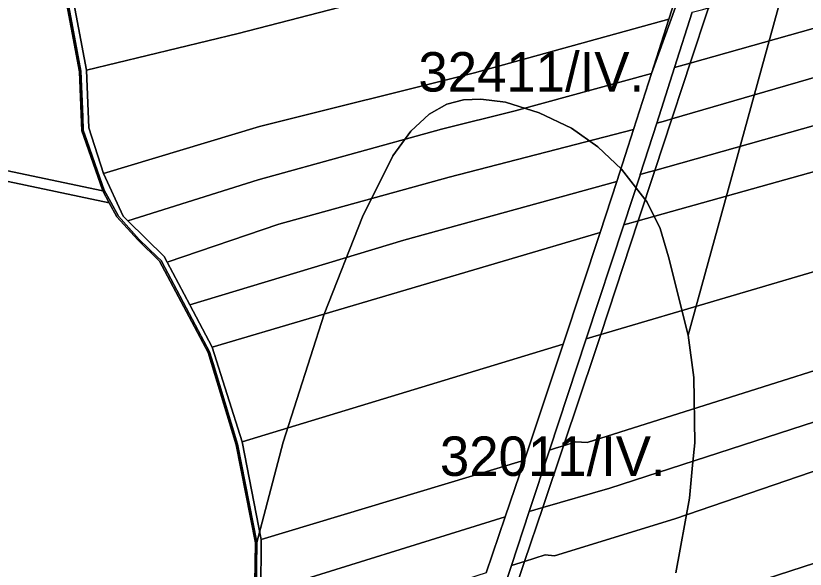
# Model space of a CAD drawing. Extents: x -535894 to -532827, y -1165802 to -1163635.
# Drawn here: x -534170.3 to -533869.9, y -1164231.2 to -1164020.6 of the extents above; entities that cross this region are included whole.
import ezdxf

# ---------------------------------------------------------------- set-up
doc = ezdxf.new("R2010")
doc.units = 0
for name, color, linetype in [('BPEJ_s', 7, 'Continuous'), ('orna_s', 7, 'Continuous'), ('ostatni_s', 7, 'Continuous'), ('PUPFL_s', 7, 'Continuous')]:
    doc.layers.add(name, color=color, linetype=linetype)

msp = doc.modelspace()

# ---------------------------------------------------------------- linework, layer by layer
at = {"layer": 'BPEJ_s'}
for points in [[(-533875.366, -1164000), (-533914.47, -1164142.17), (-533921.943, -1164112.324), (-533924.425, -1164103.745), (-533925.06, -1164101.55), (-533930.08, -1164091.52), (-533939.763, -1164078.96), (-533948.79, -1164070.49), (-533958.872, -1164063.308), (-533971.09, -1164057.51), (-533983.99, -1164053.45), (-533993.341, -1164052.28), (-533999.92, -1164052.57), (-534006.29, -1164054.239), (-534012.98, -1164057.99), (-534019.91, -1164064.519), (-534026.76, -1164073.91), (-534038.39, -1164097.17), (-534052.88, -1164134.121), (-534068.49, -1164182.86), (-534078.523, -1164221.003), (-534085.899, -1164183.652), (-534088.342, -1164175.577), (-534095.182, -1164152.964), (-534096.544, -1164148.462), (-534100.815, -1164140.418), (-534113.603, -1164116.335), (-534114.995, -1164113.714), (-534116.451, -1164112.304), (-534123.297, -1164105.677), (-534131.206, -1164096.91), (-534134.129, -1164091.534), (-534136.591, -1164086.985), (-534140.179, -1164076.764), (-534143.251, -1164068.015), (-534144.622, -1164064.109), (-534144.816, -1164059.106), (-534145.49, -1164041.708), (-534153.303, -1164000)], [(-534153.303, -1164000), (-534145.49, -1164041.708), (-534144.816, -1164059.106), (-534144.622, -1164064.109), (-534143.251, -1164068.015), (-534140.179, -1164076.764), (-534136.591, -1164086.985), (-534134.129, -1164091.534), (-534131.206, -1164096.91), (-534123.297, -1164105.677), (-534116.451, -1164112.304), (-534114.995, -1164113.714), (-534113.603, -1164116.335), (-534100.815, -1164140.418), (-534096.544, -1164148.462), (-534095.182, -1164152.964), (-534088.342, -1164175.577), (-534085.899, -1164183.652), (-534078.523, -1164221.003), (-534078.967, -1164248.905)], [(-533919.09, -1164232.56), (-533913.99, -1164204.13), (-533912.751, -1164191.59), (-533911.92, -1164183.18), (-533912.32, -1164158.25), (-533914.47, -1164142.17), (-533875.366, -1164000)], [(-534078.967, -1164248.905), (-534078.523, -1164221.003), (-534068.49, -1164182.86), (-534052.88, -1164134.121), (-534038.39, -1164097.17), (-534026.76, -1164073.91), (-534019.91, -1164064.519), (-534012.98, -1164057.99), (-534006.29, -1164054.239), (-533999.92, -1164052.57), (-533993.341, -1164052.28), (-533983.99, -1164053.45), (-533971.09, -1164057.51), (-533958.872, -1164063.308), (-533948.79, -1164070.49), (-533939.763, -1164078.96), (-533930.08, -1164091.52), (-533925.06, -1164101.55), (-533924.425, -1164103.745), (-533921.943, -1164112.324), (-533914.47, -1164142.17), (-533912.32, -1164158.25), (-533911.92, -1164183.18), (-533912.751, -1164191.59), (-533913.99, -1164204.13), (-533919.09, -1164232.56)]]:
    msp.add_lwpolyline(points, dxfattribs=at)
at = {"layer": 'orna_s'}
for points in [[(-533895.7, -1163940.37), (-533908.87, -1163981.51), (-534085.67, -1164027.32), (-534143.34, -1164041.3), (-534150.32, -1164004.31), (-533932.68, -1163949.92)], [(-533921.81, -1164021.92), (-533995.77, -1164042.33), (-534077.52, -1164062.7), (-534136.93, -1164080.66), (-534142.42, -1164063.29), (-534143.34, -1164041.3), (-534085.67, -1164027.32), (-533908.87, -1163981.51)], [(-533836.92, -1164005.27), (-533833.99, -1164016.17), (-533913.66, -1164038.64), (-533906.69, -1164017.55), (-533879.17, -1164009.99), (-533838.01, -1164000.05)], [(-533829.37, -1164033.3), (-533920.66, -1164059.82), (-533916.23, -1164046.38), (-533913.66, -1164038.64), (-533833.99, -1164016.17)], [(-533995.77, -1164042.33), (-533921.81, -1164021.92), (-533928.41, -1164042.51), (-533980.32, -1164056.75), (-534008.3, -1164063.7), (-534078.07, -1164083.07), (-534127.6, -1164098.58), (-534129.39, -1164096.82), (-534136.93, -1164080.66), (-534077.52, -1164062.7)], [(-533824.72, -1164050.56), (-533927.12, -1164079.43), (-533920.66, -1164059.82), (-533829.37, -1164033.3)], [(-533980.32, -1164056.75), (-533928.41, -1164042.51), (-533935.24, -1164063.87), (-534005.35, -1164082), (-534070.18, -1164099.94), (-534112.65, -1164114.3), (-534113.76, -1164112.22), (-534127.6, -1164098.58), (-534078.07, -1164083.07), (-534008.3, -1164063.7)], [(-533823.91, -1164053.54), (-533818.83, -1164066.55), (-533933.43, -1164098.59), (-533927.12, -1164079.43), (-533824.72, -1164050.56)], [(-534005.35, -1164082), (-533935.24, -1164063.87), (-533941.57, -1164083.63), (-534022.58, -1164105.96), (-534104.05, -1164130.62), (-534112.65, -1164114.3), (-534070.18, -1164099.94)], [(-533933.43, -1164098.59), (-533818.83, -1164066.55), (-533805.75, -1164099.98), (-533947.71, -1164141.88)], [(-533941.6, -1164083.7), (-533947.99, -1164103.02), (-534095.57, -1164146.67), (-534104.05, -1164130.62), (-534022.58, -1164105.96), (-533941.57, -1164083.63)], [(-533803.18, -1164106.57), (-533791.66, -1164132.02), (-533952.85, -1164183.05), (-533957.22, -1164182.74), (-533961.89, -1164184.21), (-533949.83, -1164148.31), (-533947.71, -1164141.88), (-533805.75, -1164099.98)], [(-533962.05, -1164145.52), (-534084.16, -1164182.76), (-534095.57, -1164146.67), (-533947.99, -1164103.02)], [(-533787.38, -1164141.47), (-533783.44, -1164148.24), (-533944.24, -1164200.35), (-533969.8, -1164207.76), (-533961.89, -1164184.21), (-533957.22, -1164182.74), (-533952.85, -1164183.05), (-533791.66, -1164132.02)], [(-534084.16, -1164182.76), (-533962.05, -1164145.52), (-533976.56, -1164189.37), (-533976.67, -1164189.68), (-534076.92, -1164219.96)], [(-533774.86, -1164162.96), (-533792.93, -1164169.52), (-533834.65, -1164183.03), (-533919.48, -1164212.04), (-533965.3, -1164226.17), (-533968.9, -1164225.77), (-533976.69, -1164228.26), (-533969.8, -1164207.76), (-533944.24, -1164200.35), (-533783.44, -1164148.24)], [(-533772.63, -1164166.78), (-533758.05, -1164191.21), (-533828.47, -1164216.61), (-533903.93, -1164241.06), (-533990.05, -1164268), (-533976.69, -1164228.26), (-533968.9, -1164225.77), (-533965.3, -1164226.17), (-533919.48, -1164212.04), (-533834.65, -1164183.03), (-533792.93, -1164169.52), (-533774.86, -1164162.96)], [(-533984.05, -1164211.29), (-534076.98, -1164240.23), (-534076.92, -1164219.96), (-533976.67, -1164189.68)], [(-533758.05, -1164191.21), (-533750.29, -1164204.21), (-533855.48, -1164242.69), (-533960.81, -1164276.96), (-533997.28, -1164289.55), (-533990.05, -1164268), (-533903.93, -1164241.06), (-533828.47, -1164216.61)], [(-533991.32, -1164232.59), (-534077.04, -1164260.25), (-534076.98, -1164240.23), (-533984.05, -1164211.29)]]:
    msp.add_lwpolyline(points, close=True, dxfattribs=at)
at = {"layer": 'ostatni_s'}
for points in [[(-533892.46, -1163911.51), (-533891.45, -1163899.11), (-533890.48, -1163923.29), (-533892.48, -1163938), (-533897.78, -1163957.92), (-533928.41, -1164042.51), (-533921.81, -1164021.92), (-533908.87, -1163981.51), (-533895.7, -1163940.37), (-533894.49, -1163936.59), (-533893.61, -1163925.64)], [(-533908.91, -1164018.16), (-533906.69, -1164017.55), (-533913.66, -1164038.64), (-533915.99, -1164039.3), (-533919.67, -1164040.34), (-533912.94, -1164019.27)], [(-533915.99, -1164039.3), (-533913.66, -1164038.64), (-533916.23, -1164046.38), (-533920.66, -1164059.82), (-533923.11, -1164060.54), (-533926.43, -1164061.51), (-533919.67, -1164040.34)], [(-533923.11, -1164060.54), (-533920.66, -1164059.82), (-533927.12, -1164079.43), (-533929.71, -1164080.17), (-533932.66, -1164081), (-533926.43, -1164061.51)], [(-533929.71, -1164080.17), (-533927.12, -1164079.43), (-533933.43, -1164098.59), (-533936.16, -1164099.35), (-533938.96, -1164100.13), (-533932.74, -1164081.26), (-533932.66, -1164081)], [(-533936.16, -1164099.35), (-533933.43, -1164098.59), (-533947.71, -1164141.88), (-533950.75, -1164142.78), (-533953.25, -1164143.52), (-533938.96, -1164100.13)], [(-533950.75, -1164142.78), (-533947.71, -1164141.88), (-533949.83, -1164148.31), (-533961.89, -1164184.21), (-533964.91, -1164185.16), (-533967.21, -1164185.88), (-533953.25, -1164143.52)], [(-533964.91, -1164185.16), (-533961.89, -1164184.21), (-533969.8, -1164207.76), (-533972.74, -1164208.61), (-533974.91, -1164209.24), (-533967.21, -1164185.88)], [(-533972.74, -1164208.61), (-533969.8, -1164207.76), (-533976.69, -1164228.26), (-533979.6, -1164229.18), (-533981.7, -1164229.85), (-533974.91, -1164209.24)], [(-533976.69, -1164228.26), (-533990.05, -1164268), (-533992.85, -1164268.88), (-533994.76, -1164269.48), (-533981.7, -1164229.85), (-533979.6, -1164229.18)]]:
    msp.add_lwpolyline(points, close=True, dxfattribs=at)
for points in [[(-533991.32, -1164232.59), (-533984.05, -1164211.29), (-533976.67, -1164189.68), (-533976.56, -1164189.37), (-533962.05, -1164145.52), (-533947.99, -1164103.02), (-533941.6, -1164083.7), (-533941.57, -1164083.63), (-533935.24, -1164063.87), (-533928.41, -1164042.51), (-533897.78, -1163957.92)], [(-534079.7, -1164259.55), (-534079.09, -1164221.21), (-534086.47, -1164183.86), (-534097.11, -1164148.68), (-534115.56, -1164113.93), (-534123.86, -1164105.89), (-534131.77, -1164097.12), (-534134.69, -1164091.75), (-534137.15, -1164087.2), (-534145.18, -1164064.32), (-534146.05, -1164041.92), (-534157.94, -1163978.43)], [(-534150.32, -1164004.31), (-534143.34, -1164041.3), (-534142.42, -1164063.29), (-534136.93, -1164080.66), (-534129.39, -1164096.82), (-534127.6, -1164098.58), (-534113.76, -1164112.22), (-534112.65, -1164114.3), (-534104.05, -1164130.62), (-534095.57, -1164146.67), (-534084.16, -1164182.76), (-534076.92, -1164219.96), (-534076.98, -1164240.23)], [(-533912.94, -1164019.27), (-533919.67, -1164040.34), (-533926.43, -1164061.51), (-533932.66, -1164081), (-533932.74, -1164081.26), (-533938.96, -1164100.13), (-533953.25, -1164143.52), (-533967.21, -1164185.88), (-533974.91, -1164209.24), (-533981.7, -1164229.85), (-533994.76, -1164269.48)]]:
    msp.add_lwpolyline(points, dxfattribs=at)
at = {"layer": 'PUPFL_s'}
msp.add_lwpolyline([(-534576.69, -1163994.7), (-534428.93, -1164025.8), (-534431.31, -1163750.05), (-534427.72, -1163752.13), (-534425.41, -1164026.54), (-534137.15, -1164087.2), (-534134.69, -1164091.75), (-534426.2, -1164030.27), (-534422.39, -1164273.15), (-534424.3, -1164273.92), (-534426.3, -1164271.96), (-534429.37, -1164029.61), (-534577.82, -1163998.3)], dxfattribs=at)
for points in [[(-534427.72, -1163752.13), (-534413.24, -1163763.36), (-534362.72, -1163807.37), (-534355.93, -1163819.24), (-534338.84, -1163838.27), (-534314.16, -1163855.97), (-534296.47, -1163870.97), (-534271.49, -1163905.38), (-534250.57, -1163903.14), (-534241.76, -1163894.34), (-534224.22, -1163957.18), (-534156.41, -1163945.04), (-534157.94, -1163978.43), (-534146.05, -1164041.92), (-534145.18, -1164064.32), (-534137.15, -1164087.2), (-534425.41, -1164026.54)], [(-534426.2, -1164030.27), (-534134.69, -1164091.75), (-534131.77, -1164097.12), (-534123.86, -1164105.89), (-534115.56, -1164113.93), (-534097.11, -1164148.68), (-534086.47, -1164183.86), (-534079.09, -1164221.21), (-534079.7, -1164259.55), (-534075.33, -1164283.15), (-534074.04, -1164285.93), (-534144.82, -1164304.74), (-534177.29, -1164303.6), (-534197.87, -1164299.21), (-534274.99, -1164277.69), (-534335.13, -1164267.45), (-534369.81, -1164273.2), (-534388.51, -1164274.7), (-534418.8, -1164271.7), (-534422.39, -1164273.15)]]:
    msp.add_lwpolyline(points, close=True, dxfattribs=at)

# ---------------------------------------------------------------- texts
at = {"layer": 'BPEJ_s'}
for s, p in [('32411/IV.', (-534017.076, -1164049.431)), ('32011/IV.', (-534008.9, -1164195.699))]:
    msp.add_text(s, height=15, dxfattribs=at).set_placement(p)

doc.saveas('drawing.dxf')
